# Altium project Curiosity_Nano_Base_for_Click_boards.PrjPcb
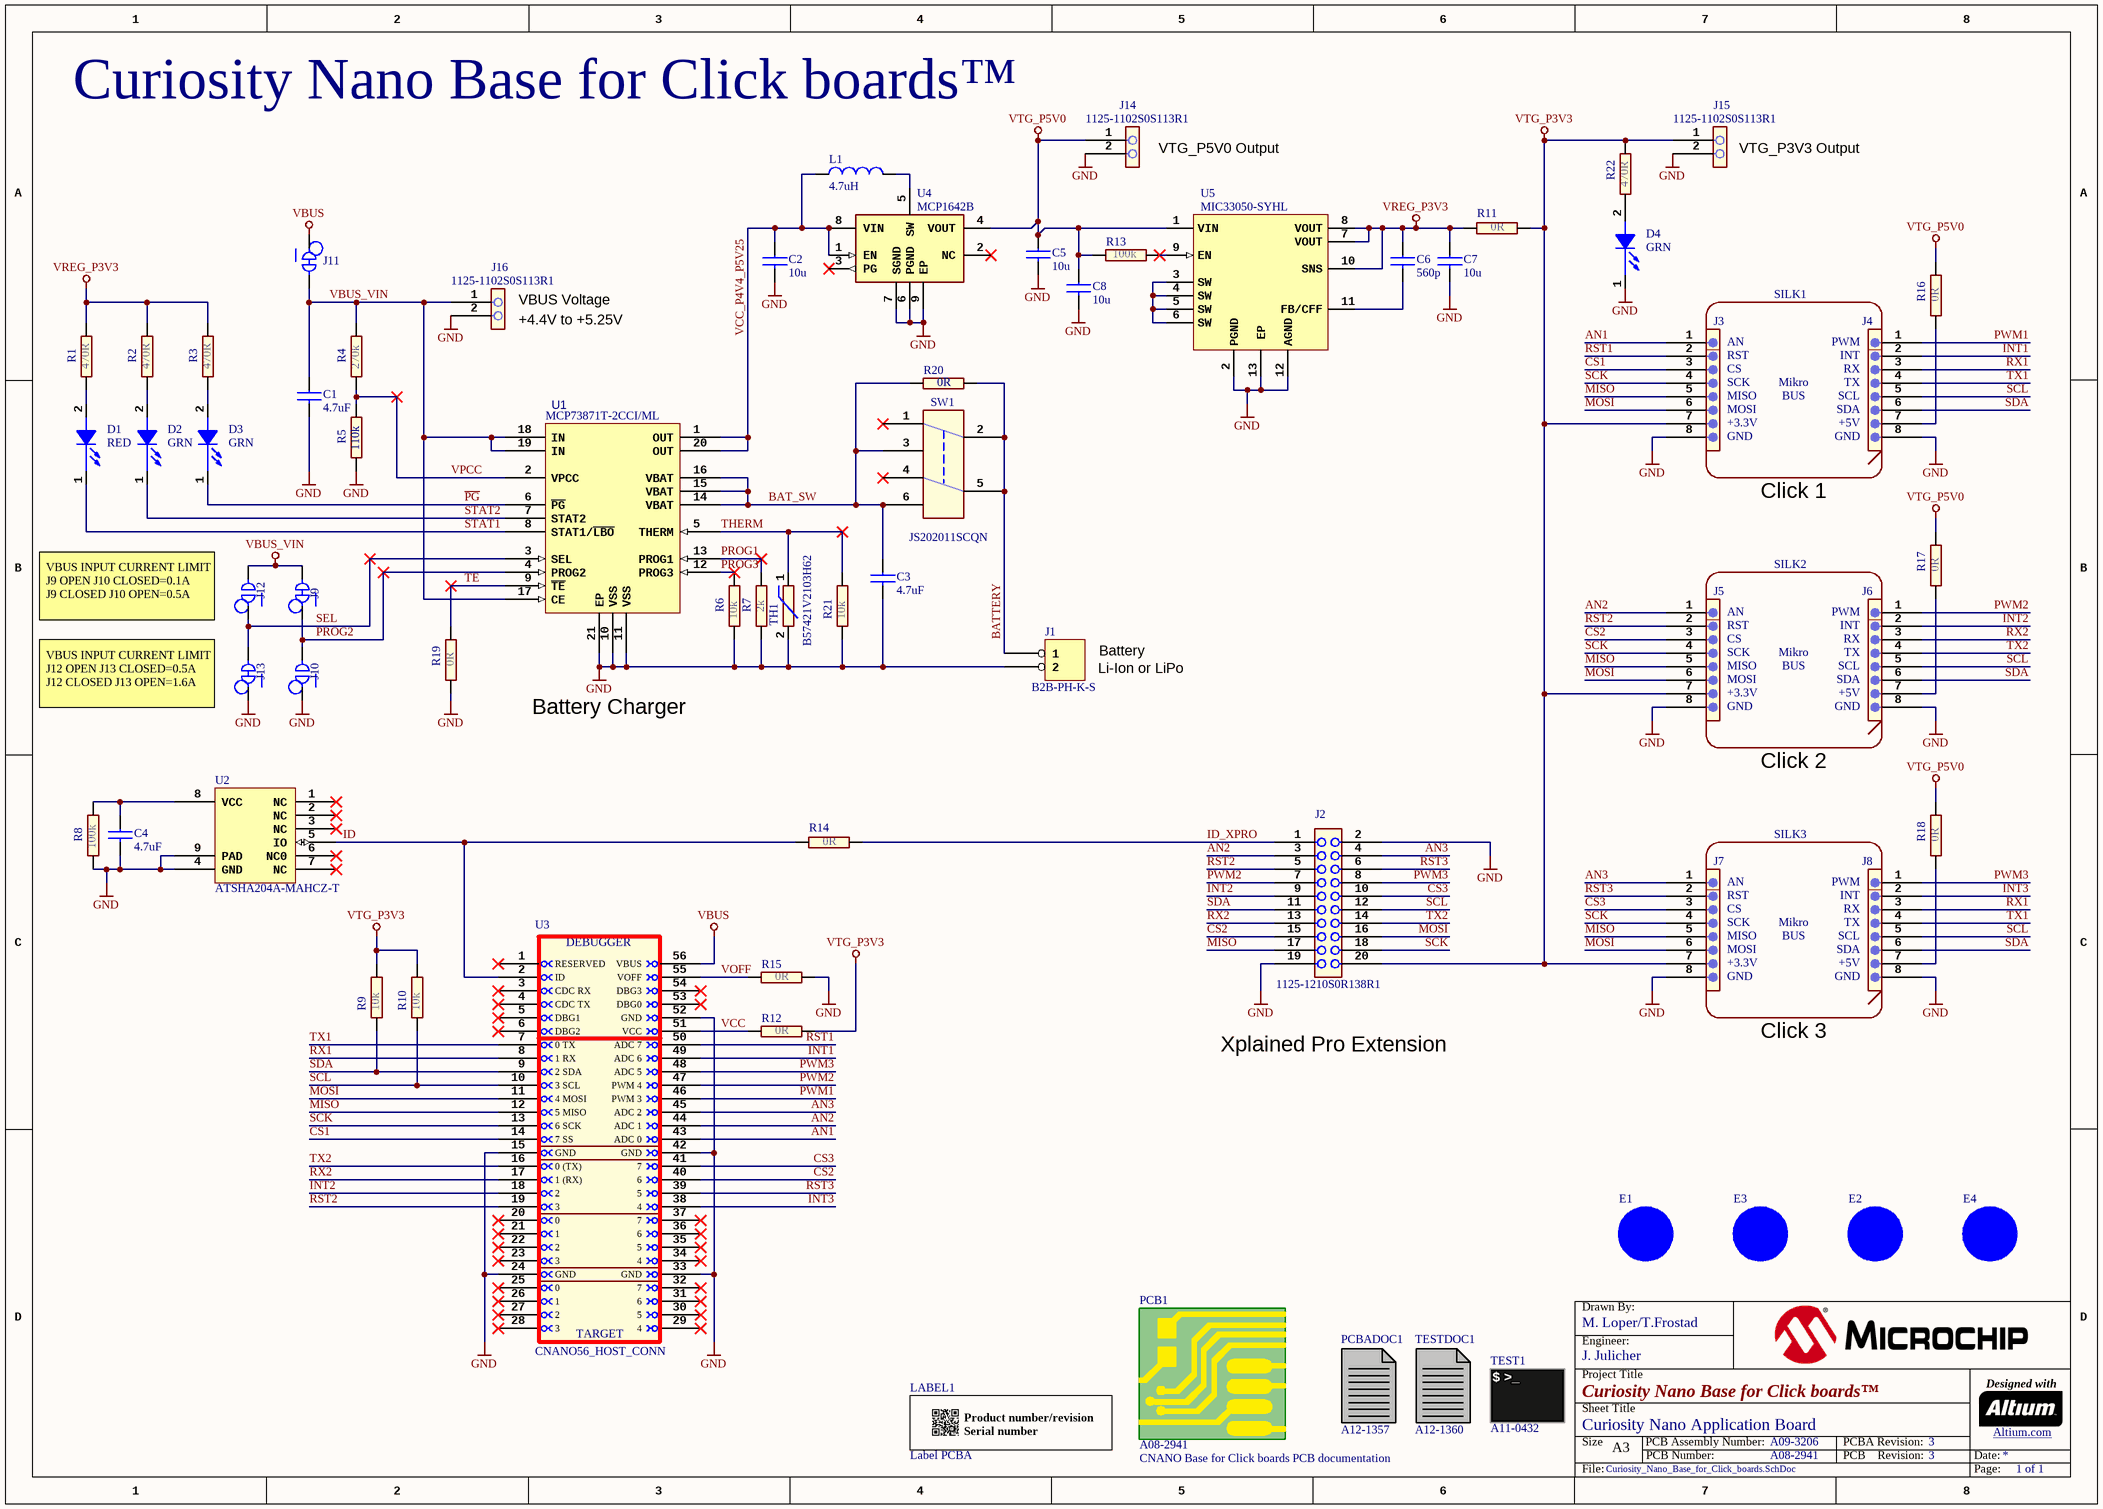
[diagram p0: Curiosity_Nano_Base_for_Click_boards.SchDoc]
ProjectTitle: Curiosity Nano Base for Click boards; ProjectRevisionSCH: 3; ProjectRevisionFAB: 3; ProjectRevisionASSY: 3; ProjectRevisionART: 3; ProjectPartNumber: **; ProjectEngineer: J. Julicher; ProjectDrawnBy: M. Loper; ProjectBoardNumber: 2267; PCBNumber_TLM: A08-2941; PCBANumber_TLM: A09-3206
1 sheet, 70 parts. Net scope: global (net labels, ports and power ports of the same name join across sheets).
Board file: Curiosity_Nano_Base_for_Click_boards.PcbDoc

## Sheet Curiosity_Nano_Base_for_Click_boards.SchDoc: Curiosity Nano Application Board
size A3; Organization: Microchip; Address1: 2355 W Chandler Blvd; Address2: Chandler, AZ 85224; Address3: USA; DocumentNumber: A09-3206; Revision: 3; SheetNumber: 1; SheetTotal: 1; DrawnBy: M. Loper/T.Frostad; Engineer: J. Julicher; PageSetup: Record=PageOptions¦CenterHorizontal=True¦CenterVertical=True¦PrintScale=1.01¦XCorrection=1.00¦YCorrection=1.00¦PrintKind=1¦BorderSize=5000000¦LeftOffset=0¦BottomOffset=0¦Orientation=2¦PaperLength=1000¦PaperWidth=1000¦Scale=100¦PaperSource=7¦PrintQuality=-4¦MediaType=1¦DitherType=10¦PaperKind=A3 (297 x 420 mm)¦PrintScaleMode=1; ProjectTitle: Curiosity Nano Base for Click boards™; PCBNumber: A08-2941; PCBRevision: 3

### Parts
C1  value 4.7uF  [AP1-00069]  (hidden comment: Generic part, no manufacturer specified.)
C2  value 10u  [AP1-00026]
C3  value 4.7uF  [AP1-00069]  (hidden comment: Generic part, no manufacturer specified.)
C4  value 4.7uF  [AP1-00069]  (hidden comment: Generic part, no manufacturer specified.)
C5  value 10u  [AP1-00026]
C6  value 560p  [AP1-00002]
C7  value 10u  [AP1-00026]
C8  value 10u  [AP1-00026]
D1  Color: RED  [AP4-00017]
D2  Color: GRN  [AP4-00017]  (hidden comment: Farnell no. 1652078)
D3  Color: GRN  [AP4-00017]  (hidden comment: Farnell no. 1652078)
D4  Color: GRN  [AP4-00017]  (hidden comment: Farnell no. 1652078)
E1  (no value)  [AP8-00192]
E2  (no value)  [AP8-00192]
E3  (no value)  [AP8-00192]
E4  (no value)  [AP8-00192]
J1  value B2B-PH-K-S  [AP8-01010]
J2  value 1125-1210S0R138R1  [AP8-01078]
J3  (no value)  [AP8-01081]
J4  (no value)  [AP8-01081]
J5  (no value)  [AP8-01081]
J6  (no value)  [AP8-01081]
J7  (no value)  [AP8-01081]
J8  (no value)  [AP8-01081]
J9  (no value)  [AP9-00044]  (net tie, no BOM)
J10  (no value)  [AP9-00043]  (no BOM)
J11  (no value)  [AP9-00044]  (net tie, no BOM)
J12  (no value)  [AP9-00043]  (no BOM)
J13  (no value)  [AP9-00044]  (net tie, no BOM)
J14  value 1125-1102S0S113R1  [AP8-01074]
J15  value 1125-1102S0S113R1  [AP8-01074]
J16  value 1125-1102S0S113R1  [AP8-01074]
L1  value 4.7uH  [AP3-00109]
LABEL1  value Label PCBA  [AP8-00317]
PCB1  value CNANO Base for Click boards PCB documentation  AN: A08-2941  (mechanical)
PCBADOC1  AN: A12-1357  (mechanical)
R1  value 470R  [AP2-00000]
R2  value 470R  [AP2-00000]
R3  value 470R  [AP2-00000]
R4  value 270k  [AP2-00000]
R5  value 110k  [AP2-00000]
R6  value 10k  [AP2-00000]
R7  value 2k  [AP2-00000]
R8  value 100k  [AP2-00000]
R9  value 10k  [AP2-00000]
R10  value 10k  [AP2-00000]
R11  value 0R  [AP2-00000]
R12  value 0R  [AP2-00000]
R13  value 100k  [AP2-00000]
R14  value 0R  [AP2-00000]
R15  value 0R  [AP2-00000]
R16  value 0R  [AP2-00000]
R17  value 0R  [AP2-00000]
R18  value 0R  [AP2-00000]
R19  value 0R  [AP2-00000]
R20  value 0R  [AP2-00001]  (no BOM)
R21  value 10k  [AP2-00000]
R22  value 470R  [AP2-00000]
SILK1  (no value)  [AP9-00167]  (no BOM)
SILK2  (no value)  [AP9-00167]  (no BOM)
SILK3  (no value)  [AP9-00167]  (no BOM)
SW1  value JS202011SCQN  [AP8-00684]
TEST1  AN: A11-0432  (mechanical)
TESTDOC1  AN: A12-1360  (mechanical)
TH1  MPN: B57421V2103H62  [AP2-00034]
U1  MPN: MCP73871T-2CCI/ML  [AP6-00165]
U2  MPN: ATSHA204A-MAHCZ-T  [AP6-00409]
U3  value CNANO56_HOST_CONN  [AP8-01154]  (no BOM)
U4  value MCP1642B  [AP6-00519]
U5  value MIC33050-SYHL  [AP6-00528]

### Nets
GND: C1.2 C2.2 C3.2 C4.2 C5.2 C7.2 C8.2 D4.1(CATHODE) J1.2 J2.2 J2.19 J3.8 J4.8 J5.8 J6.8 J7.8 J8.8 J10.1 J13.1 J14.2 J15.2 J16.2 R5.1 R6.2 R7.2 R8.2 R15.2 R19.2 R21.2 TH1.2 U1.10(VSS) U1.11(VSS) U1.21(EP) U2.4(GND) U2.9(PAD) U3.15(GND) U3.24(GND) U3.33(GND) U3.42(GND) U3.52(GND) U4.6(PGND) U4.7(SGND) U4.9(EP) U5.2(PGND) U5.12(AGND) U5.13(EP)
VBUS: J11.1 U3.56(VBUS)
VBUS_VIN: C1.1 J9.2 J11.2 J12.2 J16.1 R4.1 U1.17(CE) U1.18(IN) U1.19(IN)
VREG_P3V3: C6.1 C7.1 R1.1 R2.1 R3.1 R11.2 U5.7(VOUT) U5.8(VOUT) U5.10(SNS)
VTG_P3V3: J2.20 J3.7 J5.7 J7.7 J15.1 R9.1 R10.1 R11.1 R12.2 R22.1
VTG_P5V0: C5.1 C8.1 J14.1 R13.1 R16.1 R17.1 R18.1 U4.4(VOUT) U5.1(VIN)
AN1: J3.1 U3.43(ADC_0)
AN2: J2.3 J5.1 U3.44(ADC_1)
AN3: J2.4 J7.1 U3.45(ADC_2)
BAT_SW: C3.1 R20.1 SW1.3(NC2) SW1.6(NC1) U1.14(VBAT) U1.15(VBAT) U1.16(VBAT)
BATTERY: J1.1 R20.2 SW1.2(COMMON2) SW1.5(COMMON1)
CS1: J3.3 U3.14(7_SS)
CS2: J2.15 J5.3 U3.40(6)
CS3: J2.10 J7.3 U3.41(7)
ID: R14.1 U2.5(IO) U3.2(ID)
ID_XPRO: J2.1 R14.2
INT1: J4.2 U3.49(ADC_6)
INT2: J2.9 J6.2 U3.18(2)
INT3: J8.2 U3.38(4)
MISO: J2.17 J3.5 J5.5 J7.5 U3.12(5_MISO)
MOSI: J2.16 J3.6 J5.6 J7.6 U3.11(4_MOSI)
~{PG}: D3.1(CATHODE) U1.6(~{PG})
PROG1: R7.1 U1.13(PROG1)
PROG2: J9.1 J10.2 U1.4(PROG2)
PROG3: R6.1 U1.12(PROG3)
PWM1: J4.1 U3.46(PWM_3)
PWM2: J2.7 J6.1 U3.47(PWM_4)
PWM3: J2.8 J8.1 U3.48(ADC_5)
RST1: J3.2 U3.50(ADC_7)
RST2: J2.5 J5.2 U3.19(3)
RST3: J2.6 J7.2 U3.39(5)
RX1: J4.3 J8.3 U3.8(1_RX)
RX2: J2.13 J6.3 U3.17(1_(RX))
SCK: J2.18 J3.4 J5.4 J7.4 U3.13(6_SCK)
SCL: J2.12 J4.5 J6.5 J8.5 R10.2 U3.10(3_SCL)
SDA: J2.11 J4.6 J6.6 J8.6 R9.2 U3.9(2_SDA)
SEL: J12.1 J13.2 U1.3(SEL)
STAT1: D1.1(CATHODE) U1.8(STAT1/~{LBO})
STAT2: D2.1(CATHODE) U1.7(STAT2)
~{TE}: R19.1 U1.9(~{TE})
THERM: R21.1 TH1.1 U1.5(THERM)
TX1: J4.4 J8.4 U3.7(0_TX)
TX2: J2.14 J6.4 U3.16(0_(TX))
VCC: R12.1 U3.51(VCC)
VCC_P4V4_P5V25: C2.1 L1.1 U1.1(OUT) U1.20(OUT) U4.1(EN) U4.8(VIN)
VOFF: R15.1 U3.55(VOFF)
VPCC: R4.2 R5.2 U1.2(VPCC)
NetC4_1: C4.1 R8.1 U2.8(VCC)
NetC6_2: C6.2 U5.11(FB/CFF)
NetD1_2: D1.2(ANODE) R1.2
NetD2_2: D2.2(ANODE) R2.2
NetD3_2: D3.2(ANODE) R3.2
NetD4_2: D4.2(ANODE) R22.2
NetJ4_7: J4.7 R16.2
NetJ6_7: J6.7 R17.2
NetJ8_7: J8.7 R18.2
NetL1_2: L1.2 U4.5(SW)
NetR13_2: R13.2 U5.9(EN)
NetU5_3: U5.3(SW) U5.4(SW) U5.5(SW) U5.6(SW)

Not connected (* = marked no-connect by the designer): E1 1(FIDUCIAL); E2 1(FIDUCIAL); E3 1(FIDUCIAL); E4 1(FIDUCIAL); SW1 1(NO2)* 4(NO1)*; U2 1(NC)* 2(NC)* 3(NC)* 6(NC0)* 7(NC)*; U3 1(RESERVED)* 3(CDC_RX)* 4(CDC_TX)* 5(DBG1)* 6(DBG2)* 20(0)* 21(1)* 22(2)* 23(3)* 25(0)* 26(1)* 27(2)* 28(3)* 29(4)* 30(5)* 31(6)* 32(7)* 34(4)* 35(5)* 36(6)* 37(7)* 53(DBG0)* 54(DBG3)*; U4 2(NC)* 3(PG)*

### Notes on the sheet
- (near J14) Curiosity Nano Base for Click boards™
- (near J14) VTG_P5V0 Output
- (near J15) VTG_P3V3 Output
- (near J16) VBUS Voltage
- (near J16) +4.4V to +5.25V
- Click 1
- VBUS INPUT CURRENT LIMIT
  J9 OPEN J10 CLOSED=0.1A
  J9 CLOSED J10 OPEN=0.5A
- VBUS INPUT CURRENT LIMIT
  J12 OPEN J13 CLOSED=0.5A
  J12 CLOSED J13 OPEN=1.6A
- Battery Charger
- (near J1) Li-Ion or LiPo
- Battery
- Click 2
- Xplained Pro Extension
- Click 3
- Drawn By:
- Project Title
- Engineer:
- Designed with
- Sheet Title
- Size
- A3
- PCB Number:
- PCB Assembly Number:
- PCBA Revision:
- PCB    Revision:
- Date:
- Altium.com <http://go.altium.com/MicrochipLandingPage_Evaluation.html>
- File:
- Page:

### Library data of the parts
C1 C3 C4 = A01-0486: Ceramic capacitor, SMD 0805, X7R, 16V, 10%,; PartGroup: Capacitors,Ceramic,SMD 0805; Manufacturer: YAGEO CORP; MPN: CC0805KKX7R7BB475; TemperatureRange: -55 to +125 deg C
C2 C5 C7 C8 = A01-0289: Ceramic capacitor, SMD 1206, X7R, 16V, Â±10 %; PartGroup: Capacitors,Ceramic,SMD 1206; Manufacturer: Murata; MPN: GRM31CR71C106KA12L; TemperatureRange: -55 - 125 deg C; Tolerance: Â±10 %
C6 = A01-0098: Ceramic capacitor, SMD 0603, X7R, 50V, ±10 %; PartGroup: Capacitors,Ceramic,SMD 0603; TemperatureRange: -55 - +125 deg C
D1 = A10-0217: LED, SMD 0603, Red, Wave length=620nm, 63mcd @ (20mA, 2.2Vf) rohm; PartGroup: Opto,LEDs,SMD; MPN: SML-D12U1WT86; Value: RED LED; TemperatureRange: -40 to +85
D2-D4 = A10-0056: LED, Green, 570nm, SMD 0603; PartGroup: Opto,LEDs,SMD; Manufacturer: ROHM; Value: SML-310MTT86N; TemperatureRange: -30
E1-E4 = A08-0053: 2.8mm adhesive feet,diam 8.0mm; PartGroup: Mechanical devices,Mounting accessories; Manufacturer: 3M; Value: SJ-5076
J1 = A08-2593: Pin Header 1x2, 2mm THM, top entry, 100V AC/DC, 2A AC/DC (AWG #24); PartGroup: Mechanical devices,Connectors,Pin headers; Manufacturer: J.S.T. Mfg. Co. Ltd.
J2 = A08-2786: Pin header, 2x10, Right Angle, 2.54mm, THM, Pin In Paste; PartGroup: Mechanical devices,Connectors,Pin headers; Manufacturer: WCON HARDWARE ELECTRONICS CO., LTD
J3-J8 = A08-2791: 1x8 receptacle pin header, 2.54mm pitch THM, PIP; PartGroup: Mechanical devices,Connectors,Pin header receptacle; Manufacturer: WCON HARDWARE ELECTRONICS CO., LTD; Value: 2185-108SS0CYNP1
J9 J11 J13 = A09-0783: Default closed SMD strap, 0603 size; PartGroup: Mechanical devices,PCB implemented components; Value: SMD-STRAP_0603_CLOSED
J10 J12 = A09-0784: Default open SMD strap, 0603 size; PartGroup: Mechanical devices,PCB implemented components; Value: SMD-STRAP_0603_OPEN
J14-J16 = A08-2782: 1x2 pin header, 2.54mm pitch, Pin-in-Paste THM; PartGroup: Mechanical devices,Connectors,Pin headers; Manufacturer: WCON HARDWARE ELECTRONICS CO., LTD; TemperatureRange: -40Â°C to +105Â°C
L1 = A03-0182: 4.7uH, SMT, Power inductor, 20%,  Isat = 1.04A, 3mm x 3mm x 1.5mm; PartGroup: Inductors,Power Inductors; Manufacturer: Taiyo Yuden; MPN: NR3015T4R7M
LABEL1 = A09-0611: PCBA identification label PP Top White Gloss; PartGroup: Mechanical devices,Packaging materials,Printed Labels,PCBA; Manufacturer: ACT Logimark AS; MPN: 505462
PCB1 = A08-2941: CNANO Adapter kit PCB documentation; PartGroup: Mechanical devices,Printed circuit boards
PCBADOC1 = A12-1357: Curiosity Nano Adapter PCBA documentation; PartGroup: Documentation,PCBA Documents,Atmel; Value: A09-3206 PCBA Files
R1-R3 R22 = A02-0204: Thick film resistor, SMD 0402, 1/16W, 1%; PartGroup: Resistors,SMD,0402 1%; Manufacturer: ASJ; MPN: CR10-4700-FK; TemperatureRange: -55 - +125 deg C
R4 = A02-0270: Thick film resistor, SMD 0402, 1/16W, 1%; PartGroup: Resistors,SMD,0402 1%; TemperatureRange: -55 - +125 deg C
R5 = A02-0261: Thick film resistor, SMD 0402, 1/16W, 1%; PartGroup: Resistors,SMD,0402 1%; TemperatureRange: -55ï¿½ to +125ï¿½C
R6 R9 R10 R21 = A02-0236: Thick film resistor, SMD 0402, 1/16W, 1%; PartGroup: Resistors,SMD,0402 1%; Manufacturer: vishay; MPN: CRCW040210K0FKED; TemperatureRange: -55 - +125 deg C
R7 = A02-0219: Thick film resistor, SMD 0402, 1/16W, 1%; PartGroup: Resistors,SMD,0402 1%; TemperatureRange: -55 - +125 deg C
R8 R13 = A02-0260: Thick film resistor, SMD 0402, 1/16W, 1%; PartGroup: Resistors,SMD,0402 1%; Manufacturer: ASJ; MPN: CR10-1003-FK; TemperatureRange: -55ï¿½ to +125ï¿½C
R11 R12 R14-R19 = A02-0163: RES 0.0 OHM 1/16W 0402 SMD; PartGroup: Resistors,SMD,0402 1%; Manufacturer: (n/a); MPN: RMCF0402ZT0R00; Tolerance: 1 %; TemperatureRange: -55 - +125 deg C
R20 = A02-0001: Thick film resistor, SMD 0603, 1/10W, 1%; PartGroup: Resistors,SMD,0603 1%; Manufacturer: Panasonic; MPN: ERJ-3GEY0R00V
SILK1-SILK3 = A08-2847: Full standard silkscreen for MikroBUS socket. Derived from component files distributed by MikroElektronika. Can be deviated from in case of space requirements, etc. If so, refer to spec.; PartGroup: Mechanical devices,PCB implemented components,PCB Graphics; Value: MikroBUS_socket_silkscreen_full
SW1 = A08-1643: Slide Switch, C&K, 2 Pos 2 Pol, SMD; PartGroup: Mechanical devices,Switches,SMD; Manufacturer: C&K Components
TEST1 = A11-0432: Fixture test for Curiosity Nano Adapter; PartGroup: Software,Test software,Starter Kit; Value: Curiosity Nano Adapter test
TESTDOC1 = A12-1360: Test instructions for the curiosity nano Adapter; PartGroup: Documentation,Procedures,Test Instructions; Value: CNANO Adapter test instructions
TH1 = A02-0936: THERMISTOR NTC 10K OHM 3% 0805; PartGroup: Resistors,Thermistors,SMD NTC; Manufacturer: EPCOS; Value: NTC- B57421V2103H62; Tolerance: +-5%; TemperatureRange: -55C to +125C
U1 = A06-1643: Load Sharing and Li-Ion/Li-Polymer Battery Charge Management Controller; Manufacturer: Microchip Technology Inc; PartGroup: Integrated Circuits,Regulators,Switched; Value: MCP73871; TemperatureRange: -40Â°C to  +85Â°C
U2 = A06-1276: ATSHA204A with 1-wire interface and UDFN8 package; PartGroup: Integrated Circuits,Special function,Encryption; Manufacturer: ATMEL; Value: ATSHA204A SWI UDFN8
U3 = A08-2940: 56-pin Header HOST (for CNANO solder mounting); PartGroup: Mechanical devices,Connectors,Pin headers
U4 = A06-1646: 1 MHz Switching Boost Regulator 5V 800mA; PartGroup: Integrated Circuits,Regulators,Switched; Manufacturer: Microchip; MPN: MCP1642BT-50I/MC; TemperatureRange: -40Â°C to +85Â°C
U5 = A06-1644: 3.3V Fixed, 4MHz, 600mA, Buck regulator with internal inductor with HyperLight Load; PartGroup: Integrated Circuits,Regulators,Switched; Manufacturer: Microchip Technology Inc; MPN: MIC33050-SYHL-TR; TemperatureRange: -40C to +125C

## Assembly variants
Default Assembly: not fitted J14 J15 J16 R20 TH1 U3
